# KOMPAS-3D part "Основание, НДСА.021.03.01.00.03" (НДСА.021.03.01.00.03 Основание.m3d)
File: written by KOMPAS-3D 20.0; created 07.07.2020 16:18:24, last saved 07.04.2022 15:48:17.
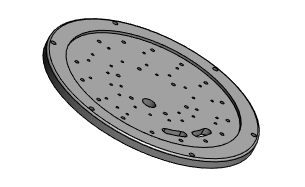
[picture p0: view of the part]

Document properties: Автор: 111; Полное имя файла: C:\Users\s.pischagina\Desktop\PLM\НДСА.021.03.01.00.03 Основание.m3d

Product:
- Part/product: Основание  | designation НДСА.021.03.01.00.03
    Материал: АМг2,5 ГОСТ 4784-97 (density 2680 kg/m3)
    Масса: 2.18949
    additional columns: <item xmlns="http://appius.ru/pdm" xmlns:xs="http://www.w3.org/2001/XMLSchema" x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; <item xmlns="http://appius.ru/pdm" xmlns:xs="http://www.w3.org/2001/XMLSchema" x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; <item xmlns="http://appius.ru/pdm" xmlns:xs="http://www.w3.org/2001/XMLSchema" x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; <item xmlns="http://appius.ru/pdm" xmlns:xs="http://www.w3.org/2001/XMLSchema" x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; <item xmlns="http://appius.ru/pdm" xmlns:xs="http://www.w3.org/2001/XMLSchema" x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
    source file: НДСА.021.03.01.00.03 Основание.cdw

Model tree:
1. Эскиз:1
2. Элемент выдавливания:1
     Расстояние 1 = 14
3. Скругление:1  (with: Элемент выдавливания:1)
     Радиус = 3
4. Эскиз:2  (with: Элемент выдавливания:1, Скругление:1)
5. Элемент выдавливания:2
     Расстояние 2 = 4
6. Эскиз:3  (with: Элемент выдавливания:2, Фаска:1)  (labels: Датчик температуры\Датчик температуры\Pt100)
7. Элемент выдавливания:3  (with: Элемент выдавливания:1)
     Расстояние 2 = 10
8. Эскиз:5  (with: Элемент выдавливания:2)
9. Элемент выдавливания:5  (with: Элемент выдавливания:1)
     Расстояние 2 = 10
10. Эскиз:6  (with: Элемент выдавливания:1, Элемент выдавливания:2)
11. Элемент выдавливания:6
     Расстояние 2 = 4
12. Эскиз:7  (with: Элемент выдавливания:6)
13. Элемент выдавливания:7
     Расстояние 2 = 3
14. Эскиз:8  (with: Элемент выдавливания:1, Элемент выдавливания:5)
15. Элемент выдавливания:8
     Расстояние 2 = 7
16. Массив по концентрической сетке:1  (with: Элемент выдавливания:6, Элемент выдавливания:7, Элемент выдавливания:8, Элемент выдавливания:1)  (6 pattern instances)
     Шаг 2 = 360
17. Эскиз:11  (with: Элемент выдавливания:1)
18. Элемент вращения:1  (with: Элемент выдавливания:1)
     Угол 1 = 360
19. Эскиз:12  (with: Элемент выдавливания:1, Элемент вращения:1)
20. Элемент выдавливания:11
     Расстояние 2 = 8.2
21. Скругление:2  (with: Элемент выдавливания:11)
     Радиус = 10
22. Скругление:3  (with: Элемент выдавливания:11)
     Радиус = 2
23. Скругление:4  (with: Элемент выдавливания:11)
     Радиус = 5
24. Эскиз:13  (with: Элемент выдавливания:1, Элемент вращения:1)
25. Элемент выдавливания:12  (with: Элемент выдавливания:2)
     Расстояние 2 = 10
26. Условное изображение резьбы:2  (with: Элемент выдавливания:12)  (labels: M5; cil0_24705-2004 coarse)
     Длина резьбы = 10; Шаг резьбы = 0.8; Номинальный диаметр резьбы = 5
27. Подгонка:2  (with: Элемент выдавливания:12)
28. Условное изображение резьбы:3  (with: Элемент выдавливания:12)  (labels: M5; cil0_24705-2004 coarse)
     Длина резьбы = 10; Шаг резьбы = 0.8; Номинальный диаметр резьбы = 5
29. Подгонка:3  (with: Элемент выдавливания:12)
30. Условное изображение резьбы:4  (with: Элемент выдавливания:12)  (labels: M5; cil0_24705-2004 coarse)
     Длина резьбы = 10; Шаг резьбы = 0.8; Номинальный диаметр резьбы = 5
31. Подгонка:4  (with: Элемент выдавливания:12)
32. Условное изображение резьбы:5  (with: Элемент выдавливания:12)  (labels: M5; cil0_24705-2004 coarse)
     Длина резьбы = 10; Шаг резьбы = 0.8; Номинальный диаметр резьбы = 5
33. Подгонка:5  (with: Элемент выдавливания:12)
34. Условное изображение резьбы:6  (with: Элемент выдавливания:12)  (labels: M5; cil0_24705-2004 coarse)
     Длина резьбы = 10; Шаг резьбы = 0.8; Номинальный диаметр резьбы = 5
35. Подгонка:6  (with: Элемент выдавливания:12)
36. Условное изображение резьбы:7  (with: Элемент выдавливания:12)  (labels: M5; cil0_24705-2004 coarse)
     Длина резьбы = 10; Шаг резьбы = 0.8; Номинальный диаметр резьбы = 5
37. Подгонка:7  (with: Элемент выдавливания:12)
38. Условное изображение резьбы:8  (with: Элемент выдавливания:12)  (labels: M5; cil0_24705-2004 coarse)
     Длина резьбы = 10; Шаг резьбы = 0.8; Номинальный диаметр резьбы = 5
39. Подгонка:8  (with: Элемент выдавливания:12)
40. Условное изображение резьбы:9  (with: Элемент выдавливания:12)  (labels: M5; cil0_24705-2004 coarse)
     Длина резьбы = 10; Шаг резьбы = 0.8; Номинальный диаметр резьбы = 5
41. Подгонка:9  (with: Элемент выдавливания:12)
42. Условное изображение резьбы:10  (with: Элемент выдавливания:12)  (labels: M5; cil0_24705-2004 coarse)
     Длина резьбы = 10; Шаг резьбы = 0.8; Номинальный диаметр резьбы = 5
43. Подгонка:10  (with: Элемент выдавливания:12)
44. Условное изображение резьбы:11  (with: Элемент выдавливания:12)  (labels: M5; cil0_24705-2004 coarse)
     Длина резьбы = 10; Шаг резьбы = 0.8; Номинальный диаметр резьбы = 5
45. Подгонка:11  (with: Элемент выдавливания:12)
46. Условное изображение резьбы:12  (with: Элемент выдавливания:12)  (labels: M5; cil0_24705-2004 coarse)
     Длина резьбы = 10; Шаг резьбы = 0.8; Номинальный диаметр резьбы = 5
47. Подгонка:12  (with: Элемент выдавливания:12)
48. Условное изображение резьбы:13  (with: Элемент выдавливания:12)  (labels: M5; cil0_24705-2004 coarse)
     Длина резьбы = 10; Шаг резьбы = 0.8; Номинальный диаметр резьбы = 5
49. Подгонка:13  (with: Элемент выдавливания:12)
50. Условное изображение резьбы:14  (with: Элемент выдавливания:12)  (labels: M5; cil0_24705-2004 coarse)
     Длина резьбы = 10; Шаг резьбы = 0.8; Номинальный диаметр резьбы = 5
51. Подгонка:14  (with: Элемент выдавливания:12)
52. Условное изображение резьбы:15  (with: Элемент выдавливания:12)  (labels: M5; cil0_24705-2004 coarse)
     Длина резьбы = 10; Шаг резьбы = 0.8; Номинальный диаметр резьбы = 5
53. Подгонка:15  (with: Элемент выдавливания:12)
54. Условное изображение резьбы:16  (with: Элемент выдавливания:12)  (labels: M5; cil0_24705-2004 coarse)
     Длина резьбы = 10; Шаг резьбы = 0.8; Номинальный диаметр резьбы = 5
55. Подгонка:16  (with: Элемент выдавливания:12)
56. Эскиз:14  (with: Элемент выдавливания:1, Отверстие:7)
57. Элемент выдавливания:13  (with: Элемент выдавливания:2)
     Расстояние 2 = 10
58. Эскиз:15  (with: Элемент выдавливания:1, Элемент выдавливания:11, Элемент выдавливания:12)
59. Элемент выдавливания:14  (with: Элемент выдавливания:2)
     Расстояние 2 = 10
60. Условное изображение резьбы:17  (with: Элемент выдавливания:14)  (labels: M5; cil0_24705-2004 coarse)
     Длина резьбы = 10; Шаг резьбы = 0.8; Номинальный диаметр резьбы = 5
61. Подгонка:17  (with: Элемент выдавливания:14)
62. Условное изображение резьбы:18  (with: Элемент выдавливания:14)  (labels: M5; cil0_24705-2004 coarse)
     Длина резьбы = 10; Шаг резьбы = 0.8; Номинальный диаметр резьбы = 5
63. Подгонка:18  (with: Элемент выдавливания:14)
64. Условное изображение резьбы:19  (with: Элемент выдавливания:14)  (labels: M5; cil0_24705-2004 coarse)
     Длина резьбы = 10; Шаг резьбы = 0.8; Номинальный диаметр резьбы = 5
65. Подгонка:19  (with: Элемент выдавливания:14)
66. Условное изображение резьбы:20  (with: Элемент выдавливания:14)  (labels: M5; cil0_24705-2004 coarse)
     Длина резьбы = 10; Шаг резьбы = 0.8; Номинальный диаметр резьбы = 5
67. Подгонка:20  (with: Элемент выдавливания:14)
68. Условное изображение резьбы:21  (with: Элемент выдавливания:14)  (labels: M5; cil0_24705-2004 coarse)
     Длина резьбы = 10; Шаг резьбы = 0.8; Номинальный диаметр резьбы = 5
69. Подгонка:21  (with: Элемент выдавливания:14)
70. Условное изображение резьбы:24  (with: Элемент выдавливания:14)  (labels: M5; cil0_24705-2004 coarse)
     Длина резьбы = 10; Шаг резьбы = 0.8; Номинальный диаметр резьбы = 5
71. Подгонка:24  (with: Элемент выдавливания:14)
72. Условное изображение резьбы:25  (with: Элемент выдавливания:14)  (labels: M5; cil0_24705-2004 coarse)
     Длина резьбы = 10; Шаг резьбы = 0.8; Номинальный диаметр резьбы = 5
73. Подгонка:25  (with: Элемент выдавливания:14)
74. Условное изображение резьбы:26  (with: Элемент выдавливания:14)  (labels: M5; cil0_24705-2004 coarse)
     Длина резьбы = 10; Шаг резьбы = 0.8; Номинальный диаметр резьбы = 5
75. Подгонка:26  (with: Элемент выдавливания:14)
76. Условное изображение резьбы:27  (with: Элемент выдавливания:14)  (labels: M5; cil0_24705-2004 coarse)
     Длина резьбы = 10; Шаг резьбы = 0.8; Номинальный диаметр резьбы = 5
77. Подгонка:27  (with: Элемент выдавливания:14)
78. Условное изображение резьбы:28  (with: Элемент выдавливания:14)  (labels: M5; cil0_24705-2004 coarse)
     Длина резьбы = 10; Шаг резьбы = 0.8; Номинальный диаметр резьбы = 5
79. Подгонка:28  (with: Элемент выдавливания:14)
80. Условное изображение резьбы:29  (with: Элемент выдавливания:14)  (labels: M5; cil0_24705-2004 coarse)
     Длина резьбы = 10; Шаг резьбы = 0.8; Номинальный диаметр резьбы = 5
81. Подгонка:29  (with: Элемент выдавливания:14)
82. Условное изображение резьбы:30  (with: Элемент выдавливания:14)  (labels: M5; cil0_24705-2004 coarse)
     Длина резьбы = 10; Шаг резьбы = 0.8; Номинальный диаметр резьбы = 5
83. Подгонка:30  (with: Элемент выдавливания:14)
84. Условное изображение резьбы:31  (with: Элемент выдавливания:14)  (labels: M5; cil0_24705-2004 coarse)
     Длина резьбы = 10; Шаг резьбы = 0.8; Номинальный диаметр резьбы = 5
85. Подгонка:31  (with: Элемент выдавливания:14)
86. Эскиз:16  (with: Элемент выдавливания:1, Элемент выдавливания:11)
87. Элемент выдавливания:15  (with: Элемент выдавливания:2)
     Расстояние 2 = 10
88. Эскиз:17  (with: Элемент выдавливания:1, Элемент вращения:1, Элемент выдавливания:11, Элемент выдавливания:15)
89. Элемент выдавливания:16
     Расстояние 2 = 4.1
90. Эскиз:18  (with: Элемент выдавливания:1, Элемент выдавливания:14)
91. Элемент выдавливания:17  (labels: АМг2,5 ГОСТ 4784-97)
     Расстояние 2 = 14

Referenced files in C:\Users\s.pischagina\Desktop\PLM\: НДСА.021.03.01.00.00 Столик.a3d
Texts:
  НДСА.021.03.01.00.03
